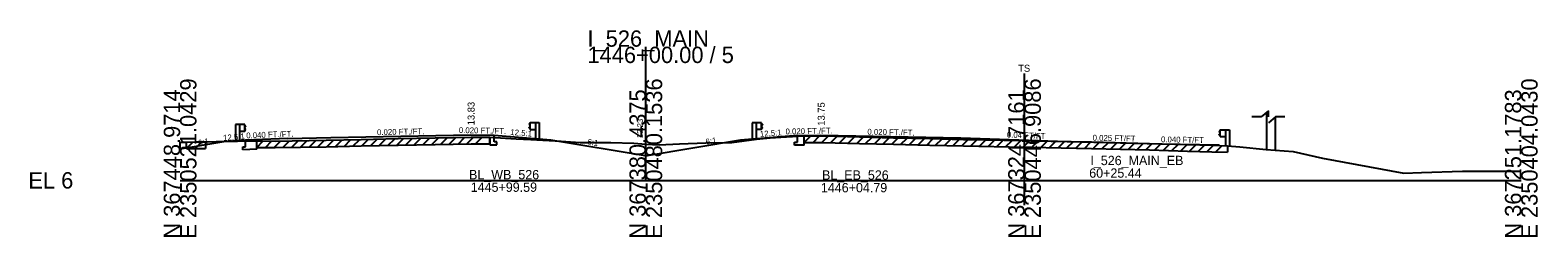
# Model space of a CAD drawing. Extents: x -170 to 2527928, y -10 to 1619750.
# Drawn here: x 4974.3 to 5232.6, y 7490.3 to 7525.8 of the extents above; entities that cross this region are included whole.
import ezdxf

# ---------------------------------------------------------------- set-up
doc = ezdxf.new("R2010")
doc.units = 0
for name, color, linetype in [('Default', 7, 'Continuous'), ('RD_GPK_XS_Cell', 7, 'Continuous'), ('RD_PD_NOISE-WALL-GM', 7, 'Continuous'), ('RD_XS_Base', 7, 'Continuous'), ('RD_XS_EarthShd', 7, 'Continuous'), ('RD_XS_ExGround', 7, 'Continuous'), ('RD_XS_ExPaveRet', 7, 'Continuous'), ('RD_XS_GR', 7, 'Continuous'), ('RD_XS_MatchLine', 7, 'Continuous'), ('RD_XS_Pave', 7, 'Continuous'), ('RD_XS_PaveShd', 7, 'Continuous'), ('RD_XS_TieSlope', 7, 'Continuous'), ('RD_XS_TX_Elev_EX', 7, 'Continuous'), ('RD_XS_TX_Slope', 7, 'Continuous'), ('RD_XS_TX_Station', 7, 'Continuous')]:
    doc.layers.add(name, color=color, linetype=linetype)

msp = doc.modelspace()

# ---------------------------------------------------------------- linework, layer by layer
at = {"layer": 'Default'}
for p, q in [((5185.22, 7510.9), (5183.64, 7510.9)), ((5186.47, 7511.93), (5185.22, 7510.9)), ((5186.47, 7510.9), (5186.47, 7511.93)), ((5187.72, 7510.9), (5186.47, 7509.88)), ((5189.31, 7510.9), (5187.72, 7510.9))]:
    msp.add_line(p, q, dxfattribs=at)
at = {"layer": 'RD_GPK_XS_Cell'}
for p, q in [((5079.8, 7500), (5079.8, 7522.92)), ((5000, 7500), (5079.8, 7500)), ((5079.8, 7500), (5144.69, 7500)), ((5144.69, 7500), (5229.81, 7500))]:
    msp.add_line(p, q, dxfattribs=at)
at = {"layer": 'RD_PD_NOISE-WALL-GM'}
for p, q in [((5186.21, 7505.3), (5186.21, 7511.72)), ((5187.71, 7505.16), (5187.71, 7510.9))]:
    msp.add_line(p, q, dxfattribs=at)
at = {"layer": 'RD_XS_Base'}
for p, q in [((5053.8, 7506.61), (5053.8, 7507.75)), ((5105.8, 7506.54), (5105.8, 7507.67)), ((5106.96, 7506.06), (5106.96, 7507.64)), ((5010.73, 7505.76), (5011.23, 7505.77)), ((5010.73, 7505.26), (5010.73, 7505.76)), ((5013.12, 7505.36), (5010.73, 7505.26)), ((5011.23, 7505.77), (5011.23, 7506.91)), ((5013.12, 7505.36), (5013.12, 7505.66)), ((5053.06, 7506.12), (5053.06, 7507.38)), ((5053.06, 7506.12), (5053.8, 7506.11)), ((5054.3, 7506.6), (5053.8, 7506.61)), ((5053.8, 7506.11), (5054.3, 7506.1)), ((5054.3, 7506.1), (5054.3, 7506.6)), ((5105.3, 7506.53), (5105.8, 7506.54)), ((5105.3, 7506.03), (5105.3, 7506.53)), ((5106.96, 7506.06), (5105.3, 7506.03)), ((5178.04, 7505.98), (5178.04, 7506.08))]:
    msp.add_line(p, q, dxfattribs=at)
at = {"layer": 'RD_XS_EarthShd'}
for p, q in [((5053.8, 7507.75), (5063.55, 7506.97)), ((5105.8, 7507.67), (5096.05, 7506.89)), ((5011.23, 7506.91), (5007.48, 7506.61))]:
    msp.add_line(p, q, dxfattribs=at)
at = {"layer": 'RD_XS_ExGround'}
msp.add_lwpolyline([(5000, 7506.52), (5000.12, 7506.53), (5001.11, 7506.57), (5002.6, 7506.58), (5002.8, 7506.58), (5004.33, 7506.6), (5004.59, 7506.62), (5006.16, 7506.68), (5009.83, 7506.74), (5013.12, 7506.78), (5016.31, 7506.74), (5025.02, 7506.88), (5031.05, 7507.02), (5037.38, 7507.16), (5043.7, 7507.27), (5049.85, 7507.39), (5051.37, 7507.39), (5053.06, 7507.38), (5057.57, 7507.12), (5060.07, 7506.99), (5065.28, 7506.72), (5068.56, 7506.5), (5073.8, 7506.5), (5077.74, 7506.37), (5079.8, 7506.23), (5082.09, 7506.08), (5085.56, 7506.25), (5090.07, 7506.45), (5094.43, 7506.49), (5094.55, 7506.49), (5098.77, 7507.05), (5101.11, 7507.27), (5102.96, 7507.38), (5106.96, 7507.64), (5108.97, 7507.62), (5110.17, 7507.61), (5116.39, 7507.45), (5122.22, 7507.32), (5128.46, 7507.17), (5134.25, 7507.03), (5144.69, 7506.81), (5145.78, 7506.79), (5156.14, 7506.58), (5166.13, 7506.33), (5172.61, 7506.15), (5176.78, 7506.02), (5179.46, 7505.93), (5181.61, 7505.74), (5186.12, 7505.31), (5190.7, 7504.94), (5195.74, 7503.79), (5209.67, 7501.26), (5212.73, 7501.37), (5219.74, 7501.6), (5229.81, 7501.6)], dxfattribs=at)
at = {"layer": 'RD_XS_ExPaveRet'}
for p, q in [((5106.96, 7506.52), (5106.96, 7507.64)), ((5106.96, 7506.52), (5108.07, 7507.63)), ((5108.46, 7506.5), (5109.57, 7507.61)), ((5109.96, 7506.49), (5111.06, 7507.58)), ((5111.46, 7506.45), (5112.56, 7507.55)), ((5112.96, 7506.41), (5114.06, 7507.51)), ((5114.46, 7506.38), (5115.56, 7507.47)), ((5115.96, 7506.34), (5117.06, 7507.43)), ((5001.1, 7505.45), (5002.24, 7506.58)), ((5001.1, 7505.45), (5001.1, 7506.57)), ((5001.1, 7505.45), (5001.11, 7505.45)), ((5001.11, 7505.45), (5002.6, 7505.46)), ((5002.6, 7505.46), (5003.73, 7506.6)), ((5002.6, 7505.46), (5002.8, 7505.46)), ((5002.8, 7505.46), (5004.33, 7505.48)), ((5004.33, 7506.6), (5004.33, 7505.48)), ((5013.12, 7505.66), (5013.12, 7506.78)), ((5013.12, 7505.66), (5014.23, 7506.77)), ((5013.12, 7505.66), (5016.31, 7505.62)), ((5014.62, 7505.64), (5015.73, 7506.75)), ((5016.12, 7505.63), (5017.26, 7506.76)), ((5016.31, 7505.62), (5025.02, 7505.76)), ((5017.62, 7505.64), (5018.76, 7506.78)), ((5019.12, 7505.67), (5020.26, 7506.81)), ((5020.62, 7505.69), (5021.76, 7506.83)), ((5022.12, 7505.71), (5023.26, 7506.85)), ((5023.62, 7505.74), (5024.76, 7506.88)), ((5025.02, 7505.76), (5031.05, 7505.9)), ((5025.12, 7505.76), (5026.27, 7506.91)), ((5026.62, 7505.8), (5027.77, 7506.94)), ((5028.12, 7505.83), (5029.27, 7506.98)), ((5029.62, 7505.86), (5030.77, 7507.01)), ((5031.05, 7505.9), (5037.38, 7506.04)), ((5031.12, 7505.9), (5032.27, 7507.04)), ((5032.62, 7505.93), (5033.77, 7507.08)), ((5034.12, 7505.96), (5035.27, 7507.11)), ((5035.62, 7506), (5036.77, 7507.14)), ((5037.12, 7506.03), (5038.26, 7507.17)), ((5037.38, 7506.04), (5043.7, 7506.15)), ((5038.62, 7506.06), (5039.76, 7507.2)), ((5040.12, 7506.09), (5041.26, 7507.23)), ((5041.62, 7506.12), (5042.76, 7507.26)), ((5043.12, 7506.14), (5044.26, 7507.29)), ((5043.7, 7506.15), (5049.85, 7506.27)), ((5044.62, 7506.17), (5045.76, 7507.31)), ((5046.12, 7506.2), (5047.26, 7507.34)), ((5047.62, 7506.23), (5048.76, 7507.37)), ((5049.12, 7506.26), (5050.26, 7507.39)), ((5049.85, 7506.27), (5051.37, 7506.27)), ((5050.62, 7506.27), (5051.74, 7507.39)), ((5051.37, 7506.27), (5053.06, 7506.26)), ((5053.06, 7507.38), (5053.06, 7506.26)), ((5106.96, 7506.52), (5108.97, 7506.5)), ((5108.97, 7506.5), (5110.17, 7506.49)), ((5110.17, 7506.49), (5116.39, 7506.33)), ((5116.39, 7506.33), (5122.22, 7506.2)), ((5117.46, 7506.3), (5118.56, 7507.4)), ((5118.96, 7506.27), (5120.06, 7507.37)), ((5120.46, 7506.24), (5121.56, 7507.33)), ((5121.96, 7506.2), (5123.06, 7507.3)), ((5122.22, 7506.2), (5128.46, 7506.05)), ((5123.46, 7506.17), (5124.56, 7507.26)), ((5124.96, 7506.13), (5126.06, 7507.23)), ((5126.46, 7506.1), (5127.56, 7507.19)), ((5127.96, 7506.06), (5129.06, 7507.16)), ((5128.46, 7506.05), (5134.25, 7505.91)), ((5129.46, 7506.02), (5130.56, 7507.12)), ((5130.96, 7505.99), (5132.06, 7507.08)), ((5132.46, 7505.95), (5133.56, 7507.04)), ((5133.96, 7505.91), (5135.06, 7507.01)), ((5134.25, 7505.91), (5144.69, 7505.69)), ((5135.46, 7505.88), (5136.56, 7506.98)), ((5136.96, 7505.85), (5138.06, 7506.95)), ((5138.46, 7505.82), (5139.56, 7506.92)), ((5139.96, 7505.79), (5141.06, 7506.89)), ((5141.46, 7505.76), (5142.56, 7506.86)), ((5142.96, 7505.73), (5144.06, 7506.83)), ((5144.46, 7505.7), (5145.56, 7506.8)), ((5144.69, 7505.69), (5145.78, 7505.67)), ((5145.78, 7505.67), (5156.14, 7505.46)), ((5145.96, 7505.67), (5147.06, 7506.77)), ((5147.46, 7505.64), (5148.56, 7506.74)), ((5148.96, 7505.61), (5150.06, 7506.71)), ((5150.46, 7505.58), (5151.56, 7506.68)), ((5151.96, 7505.55), (5153.06, 7506.65)), ((5153.46, 7505.52), (5154.56, 7506.62)), ((5154.96, 7505.49), (5156.06, 7506.59)), ((5156.14, 7505.46), (5166.13, 7505.21)), ((5156.46, 7505.45), (5157.56, 7506.55)), ((5157.96, 7505.42), (5159.06, 7506.51)), ((5159.46, 7505.38), (5160.56, 7506.47)), ((5160.96, 7505.34), (5162.06, 7506.43)), ((5162.46, 7505.3), (5163.56, 7506.4)), ((5163.96, 7505.26), (5165.06, 7506.36)), ((5165.46, 7505.23), (5166.56, 7506.32)), ((5166.13, 7505.21), (5172.61, 7505.03)), ((5166.96, 7505.19), (5168.05, 7506.28)), ((5168.46, 7505.14), (5169.55, 7506.23)), ((5169.96, 7505.1), (5171.05, 7506.19)), ((5171.46, 7505.06), (5172.55, 7506.15)), ((5172.61, 7505.03), (5176.78, 7504.9)), ((5172.96, 7505.01), (5174.05, 7506.1)), ((5174.46, 7504.97), (5175.55, 7506.06)), ((5175.96, 7504.92), (5177.05, 7506.01)), ((5176.78, 7504.9), (5179.46, 7504.81)), ((5177.46, 7504.88), (5178.55, 7505.96)), ((5179.46, 7505.93), (5179.46, 7504.81))]:
    msp.add_line(p, q, dxfattribs=at)
at = {"layer": 'RD_XS_GR'}
for p, q in [((5010.15, 7509.57), (5009.48, 7509.57)), ((5009.48, 7509.57), (5009.48, 7506.77)), ((5011.07, 7509.57), (5010.15, 7509.57)), ((5010.15, 7509.57), (5010.15, 7506.82)), ((5011.07, 7508.4), (5010.15, 7508.4)), ((5011.07, 7508.4), (5011.07, 7509.57)), ((5011.07, 7509.49), (5011.23, 7509.29)), ((5011.23, 7509.24), (5011.07, 7509.04)), ((5011.23, 7508.72), (5011.07, 7508.92)), ((5011.07, 7508.47), (5011.23, 7508.67)), ((5011.23, 7509.29), (5011.23, 7509.24)), ((5011.23, 7508.67), (5011.23, 7508.72)), ((5059.97, 7509.84), (5059.8, 7509.64)), ((5059.8, 7509.64), (5059.8, 7509.59)), ((5059.8, 7509.59), (5059.97, 7509.39)), ((5059.8, 7509.07), (5059.97, 7509.27)), ((5059.8, 7509.02), (5059.8, 7509.07)), ((5059.97, 7508.82), (5059.8, 7509.02)), ((5059.97, 7508.74), (5059.97, 7509.91)), ((5059.97, 7509.91), (5060.89, 7509.91)), ((5059.97, 7508.74), (5060.89, 7508.74)), ((5060.89, 7509.91), (5061.55, 7509.91)), ((5060.89, 7509.91), (5060.89, 7507.17)), ((5061.55, 7509.91), (5061.55, 7507.11)), ((5098.72, 7509.87), (5098.05, 7509.87)), ((5098.05, 7509.87), (5098.05, 7507.07)), ((5099.64, 7509.87), (5098.72, 7509.87)), ((5098.72, 7509.87), (5098.72, 7507.12)), ((5099.64, 7508.7), (5098.72, 7508.7)), ((5099.64, 7508.7), (5099.64, 7509.87)), ((5099.64, 7509.79), (5099.8, 7509.59)), ((5099.8, 7509.54), (5099.64, 7509.34)), ((5099.8, 7509.02), (5099.64, 7509.22)), ((5099.64, 7508.77), (5099.8, 7508.97)), ((5099.8, 7509.59), (5099.8, 7509.54)), ((5099.8, 7508.97), (5099.8, 7509.02)), ((5178.22, 7508.62), (5178.05, 7508.42)), ((5178.05, 7508.42), (5178.05, 7508.37)), ((5178.05, 7508.37), (5178.22, 7508.17)), ((5178.05, 7507.85), (5178.22, 7508.05)), ((5178.05, 7507.8), (5178.05, 7507.85)), ((5178.22, 7507.6), (5178.05, 7507.8)), ((5178.22, 7507.52), (5178.22, 7508.69)), ((5178.22, 7508.69), (5179.14, 7508.69)), ((5178.22, 7507.52), (5179.14, 7507.52)), ((5179.14, 7508.69), (5179.8, 7508.69)), ((5179.14, 7508.69), (5179.14, 7505.95)), ((5179.8, 7508.69), (5179.8, 7505.89))]:
    msp.add_line(p, q, dxfattribs=at)
at = {"layer": 'RD_XS_MatchLine'}
msp.add_line((5144.7, 7495.76), (5144.7, 7518.35), dxfattribs=at)
at = {"layer": 'RD_XS_Pave'}
for p, q in [((5025.8, 7507.35), (5049.8, 7507.83)), ((5109.8, 7507.75), (5133.8, 7507.27)), ((5018.44, 7507.2), (5025.8, 7507.35)), ((5151.98, 7506.67), (5168.01, 7506.26))]:
    msp.add_line(p, q, dxfattribs=at)
at = {"layer": 'RD_XS_PaveShd'}
for p, q in [((5049.8, 7507.83), (5053.8, 7507.75)), ((5105.8, 7507.67), (5109.8, 7507.75)), ((5018.44, 7507.2), (5011.23, 7506.91)), ((5133.8, 7507.29), (5151.98, 7506.67)), ((5168.01, 7506.26), (5178.04, 7506.08))]:
    msp.add_line(p, q, dxfattribs=at)
at = {"layer": 'RD_XS_TieSlope'}
for p, q in [((5007.48, 7506.61), (5000, 7505.36)), ((5000, 7505.36), (5000, 7506.53)), ((5063.55, 7506.97), (5080.03, 7504.22)), ((5096.05, 7506.89), (5080.03, 7504.22))]:
    msp.add_line(p, q, dxfattribs=at)

# ---------------------------------------------------------------- texts
at = {"layer": 'RD_GPK_XS_Cell'}
for s, p in [('I_526_MAIN', (5069.8, 7522.92)), ('1446+00.00 / 5', (5069.8, 7520.12)), ('EL 6', (4974, 7498.6))]:
    msp.add_text(s, height=2.8, dxfattribs=at).set_placement(p)
for s, p in [('N 367448.9714', (5000, 7490)), ('E 2350521.0429', (5002.8, 7490)), ('N 367380.4375', (5079.8, 7490)), ('E 2350480.1536', (5082.6, 7490)), ('N 367324.7161', (5144.69, 7490)), ('E 2350446.9086', (5147.49, 7490)), ('N 367251.1783', (5229.81, 7490)), ('E 2350404.0430', (5232.61, 7490))]:
    msp.add_text(s, height=2.8, rotation=90, dxfattribs=at).set_placement(p)
at = {"layer": 'RD_XS_MatchLine'}
msp.add_text('TS', height=1.2, dxfattribs=at).set_placement((5143.61, 7518.62))
at = {"layer": 'RD_XS_TX_Elev_EX'}
msp.add_text('12.23', height=1, rotation=90, dxfattribs=at).set_placement((5079.3, 7507.23))
at = {"layer": 'RD_XS_TX_Slope'}
for s, rotation, p in [('12.5:1', 4.5739, (5007.42, 7506.78)), ('0.040 FT./FT.', 2.2906, (5011.35, 7507.19)), ('0.020 FT./FT.', 1.1458, (5033.75, 7507.75)), ('0.020 FT./FT.', 358.8542, (5047.76, 7508.12)), ('12.5:1', 355.4261, (5056.56, 7507.79)), ('12.5:1', 4.5739, (5099.39, 7507.44)), ('0.020 FT./FT.', 1.1458, (5103.75, 7507.88)), ('0.020 FT./FT.', 358.8542, (5117.76, 7507.84)), ('0.04 FT/FT', 357.7094, (5141.65, 7507.35)), ('0.025 FT/FT', 358.5427, (5156.35, 7506.82)), ('0.040 FT/FT', 359.1102, (5168.07, 7506.53)), ('6:1', 11.5934, (5003.19, 7505.9)), ('6:1', 350.5446, (5069.73, 7506.18)), ('6:1', 9.4623, (5090.14, 7506.11))]:
    msp.add_text(s, height=1, rotation=rotation, dxfattribs=at).set_placement(p)
at = {"layer": 'RD_XS_TX_Station'}
for s, p in [(' 13.83', (5050.46, 7509)), (' 13.75', (5110.46, 7508.93))]:
    msp.add_text(s, height=1.2, rotation=90, dxfattribs=at).set_placement(p)
for s, p in [('I_526_MAIN_EB', (5155.98, 7502.61)), ('BL_WB_526', (5049.51, 7500.18)), ('BL_EB_526', (5110, 7500.11)), ('60+25.44', (5155.78, 7500.45)), ('1445+99.59', (5049.8, 7498.03)), ('1446+04.79', (5109.8, 7497.95))]:
    msp.add_text(s, height=1.6, dxfattribs=at).set_placement(p)

doc.saveas('drawing.dxf')
